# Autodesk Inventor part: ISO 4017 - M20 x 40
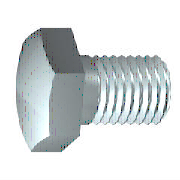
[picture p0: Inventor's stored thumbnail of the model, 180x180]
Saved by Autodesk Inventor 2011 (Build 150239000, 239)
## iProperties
IsCustomPart: 0
Created: 2010-02
Part Number: ISO 4017 - M20 x 40
Material: Stainless Steel, 440C
Description: Hexagon head screws
Document SubType Name: Modeling
Standard: ISO 4017
Designer: 129877
Standard Revision: Third edition 1999-08-15
Standards Organization: ISO
Language: en-US
Size Designation: M20 x 40
Categories: <MemberInstance><Categories><Category DisplayName="Fasteners" InternalName="e4da775c-781d-43d5-af7c-5136215cf5a6" Mnemonic="FSTN"><Category DisplayName="Bolts"
Density: 7.75 g/cm^3
Mass: 171.163 g
Surface Area: 52.6284 cm^2
Volume: 22.0856 cm^3
Author: 129877
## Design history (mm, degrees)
body "Solid1"
workplane "Work Plane1"
revolve "Body" stored, may be unused: angle "d12" = 90 deg
sketch "Sketch2"
  geometry: L1 (0, 17.321)-(15, 8.66); L2 (15, 8.66)-(15, -8.66); L3 (15, -8.66)-(0, -17.321); L4 (0, -17.321)-(-15, -8.66); L5 (-15, -8.66)-(-15, 8.66); L6 (-15, 8.66)-(0, 17.321); 2 further points
  constraints: 12 end point, 1 coincident, 1 vertical, 11 other
  dimensions: "d11" = 30 distance between parallel lines of L5 L2 (= SW)
extrude "Head" join sketch "Sketch2" distance "d3" = 11.7 (= KOH - SD); taper "d4" = 0 deg
revolve "Chamfer1" stored, may be unused: angle "d21" = 90 deg
feature "Thread" dims "d15" = 32.5 (= GEL), "d16" = 0
chamfer "Chamfer2" distance "d6" = 1.53363 (= -0.5 x SPD + 0.5 x GD); stored, may be unused: second distance "d7" = 1.53373 (computed from GUL), angle "d55" = 45 deg
sketch "Sketch1"
  geometry: L1 (0, 14.095)-(0, 10); L2 (7.5, 10)-(40, 10); L3 (40, 10)-(40, 0); L4 (40, 0)-(-0.8, 0); L5 (-8.96, 0)-(48.16, 0) reference; L6 (-0.8, 0)-(-0.8, 14.095); L7 (-0.8, 14.095)-(0, 14.095); L8 (7.5, 10)-(5.966, 10); L9 (5.966, 10)-(0, 10); L10 (0, -2.819)-(0, 16.914) reference
  constraints: 16 end point, 2 collinear, 2 perpendicular, 1 parallel
  dimensions: "d0" = 40 distance between parallel lines of L3 L1 (= NLG); "d1" = 32.5 distance from line of L2.start L3 (= GEL); "d2" = 20 diameter of L2 L4 (= GD); "d9" = 0.8001 distance between parallel lines of L6 L1 (computed from SD); "d10" = 28.19 diameter of L7 L4 (= SD2); "d13" = 1.53373 distance of L2.start L8.end (computed from GAL); "d14" = 20 diameter of L9 L4 (= BDM)
sketch "Sketch4"
  geometry: L1 (-12.5, 15)-(-12.5, 17.321); L2 (-12.5, 17.321)-(-11.16, 17.321); L3 (-11.16, 17.321)-(-12.5, 15); L4 (-14.84, 0)-(1.54, 0) reference; L5 (-0.8, 17.321)-(-12.5, 17.321) reference; L6 (-12.5, 8.66)-(-12.5, 17.321) reference
  constraints: 6 end point, 2 collinear, 1 perpendicular, 1 vertical
  dimensions: "d5" = 30 deg angle of L3 L1 (= ANG1); "d19" = 30 diameter of L1.start L4 (= SW0)
other parameters: "NLG" = 40 [user parameter; used in 1 equation term], "GD" = 20 (= NND) [user parameter; used in 2 equation terms], "BDM" = 20 (= NND) [user parameter; used in 1 equation term], "KOH" = 12.5 [user parameter; used in 1 equation term], "GEL" = 32.5 [user parameter; used in 2 equation terms], "SW" = 30 [user parameter; used in 2 equation terms], "SW0" = 30 (= SW) [user parameter; used in 1 equation term], "SPD" = 16.93275 (= NND - 1.2269 x PTC) [user parameter; used in 1 equation term], "SD2" = 28.19 [user parameter; used in 2 equation terms], "SD" = 0.8 [user parameter; used in 2 equation terms], "ANG1" = 30 deg [user parameter; used in 1 equation term], "GAL" = 1.53363 (= 0.61345 x PTC) [user parameter; used in 1 equation term], "GUL" = 1.53363 (= 0.61345 x PTC) [user parameter; used in 1 equation term], "d8" = 0, "RR" = 0.8 [user parameter], "d57" = 0, "d58" = 0, "TPU" = 4 (computed from PTC) [user parameter], "GD1" = 16.93275 (= THREADDIA - 1.2269 x PTC) [user parameter], "SDH" = 28.19 (= SD2) [user parameter], "SDHG" = 7.5 [user parameter], "TOA" = 30 deg [user parameter], "PTC" = 2.5 [user parameter; used in 5 equation terms], "E0" = 34.65 [user parameter]
